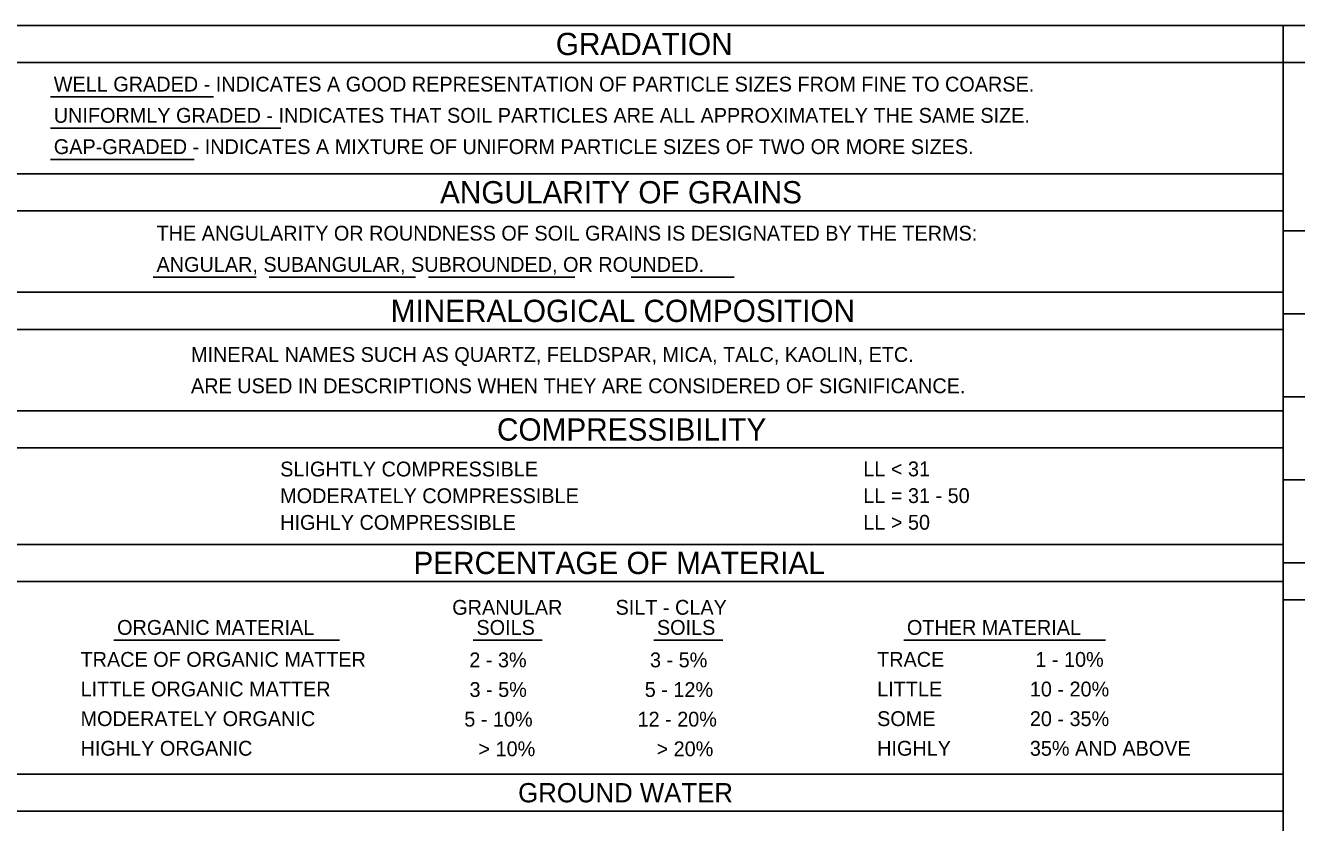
# Model space of a CAD drawing. Extents: x 278618 to 280654, y 171155 to 171855.
# Drawn here: x 280512.35 to 280549.54, y 171598.38 to 171621.7 of the extents above; entities that cross this region are included whole.
import ezdxf

# ---------------------------------------------------------------- set-up
doc = ezdxf.new("R2010")
doc.units = 0
doc.layers.add('Geotech Sheets and Borders Cell', color=7, linetype='Continuous')

msp = doc.modelspace()

# ---------------------------------------------------------------- linework, layer by layer
at = {"layer": 'Geotech Sheets and Borders Cell'}
for p, q in [((280474.148, 171621.702), (280624.148, 171621.702)), ((280549.148, 171621.702), (280549.148, 171541.488)), ((280474.148, 171620.618), (280624.148, 171620.618)), ((280513.086, 171619.609), (280517.847, 171619.609)), ((280513.086, 171618.695), (280519.821, 171618.695)), ((280513.086, 171617.78), (280517.287, 171617.78)), ((280549.148, 171617.364), (280511.888, 171617.364)), ((280549.148, 171616.28), (280511.888, 171616.28)), ((280588.802, 171615.694), (280549.148, 171615.694)), ((280516.091, 171614.334), (280519.104, 171614.334)), ((280519.48, 171614.334), (280523.763, 171614.334)), ((280524.139, 171614.334), (280528.423, 171614.334)), ((280530.069, 171614.334), (280533.082, 171614.334)), ((280549.148, 171613.894), (280511.888, 171613.894)), ((280588.802, 171613.265), (280549.148, 171613.265)), ((280549.148, 171612.809), (280511.888, 171612.809)), ((280588.802, 171610.836), (280549.148, 171610.836)), ((280549.148, 171610.423), (280511.888, 171610.423)), ((280549.148, 171609.339), (280511.888, 171609.339)), ((280588.802, 171608.406), (280549.148, 171608.406)), ((280549.148, 171606.519), (280511.888, 171606.519)), ((280588.802, 171605.977), (280549.148, 171605.977)), ((280549.148, 171605.435), (280511.888, 171605.435)), ((280588.802, 171604.892), (280549.148, 171604.892)), ((280514.937, 171603.714), (280521.536, 171603.714)), ((280525.45, 171603.714), (280527.472, 171603.714)), ((280530.731, 171603.714), (280532.753, 171603.714)), ((280538.046, 171603.714), (280543.949, 171603.714)), ((280549.148, 171599.795), (280511.888, 171599.795)), ((280549.148, 171598.711), (280511.888, 171598.711))]:
    msp.add_line(p, q, dxfattribs=at)

# ---------------------------------------------------------------- texts
for s, height, p in [('GRADATION', 0.6507, (280527.867, 171620.834)), ('WELL GRADED - INDICATES A GOOD REPRESENTATION OF PARTICLE SIZES FROM FINE TO COARSE.', 0.43381, (280513.179, 171619.768)), ('UNIFORMLY GRADED - INDICATES THAT SOIL PARTICLES ARE ALL APPROXIMATELY THE SAME SIZE.', 0.43381, (280513.179, 171618.853)), ('GAP-GRADED - INDICATES A MIXTURE OF UNIFORM PARTICLE SIZES OF TWO OR MORE SIZES.', 0.43381, (280513.179, 171617.938)), ('ANGULARITY OF GRAINS', 0.6507, (280524.48, 171616.496)), ('THE ANGULARITY OR ROUNDNESS OF SOIL GRAINS IS DESIGNATED BY THE TERMS:', 0.43381, (280516.185, 171615.406)), ('ANGULAR, SUBANGULAR, SUBROUNDED, OR ROUNDED.', 0.43381, (280516.185, 171614.492)), ('MINERALOGICAL COMPOSITION', 0.6507, (280523.035, 171613.026)), ('MINERAL NAMES SUCH AS QUARTZ, FELDSPAR, MICA, TALC, KAOLIN, ETC.', 0.43381, (280517.193, 171611.856)), ('ARE USED IN DESCRIPTIONS WHEN THEY ARE CONSIDERED OF SIGNIFICANCE.', 0.43381, (280517.193, 171610.942)), ('COMPRESSIBILITY', 0.6507, (280526.145, 171609.555)), ('SLIGHTLY COMPRESSIBLE', 0.43381, (280519.803, 171608.506)), ('LL < 31', 0.4338, (280536.864, 171608.51)), ('MODERATELY COMPRESSIBLE', 0.43381, (280519.803, 171607.725)), ('LL = 31 - 50', 0.43381, (280536.864, 171607.729)), ('HIGHLY COMPRESSIBLE', 0.43381, (280519.803, 171606.944)), ('LL > 50', 0.4338, (280536.864, 171606.948)), ('PERCENTAGE OF MATERIAL', 0.6507, (280523.701, 171605.651)), ('GRANULAR', 0.4338, (280524.837, 171604.459)), ('SILT - CLAY', 0.43381, (280529.615, 171604.46)), ('ORGANIC MATERIAL', 0.43381, (280515.031, 171603.872)), ('SOILS', 0.4338, (280525.544, 171603.872)), ('SOILS', 0.4338, (280530.825, 171603.872)), ('OTHER MATERIAL', 0.43381, (280538.14, 171603.872)), ('TRACE OF ORGANIC MATTER', 0.43381, (280513.962, 171602.937)), ('2 - 3%', 0.4338, (280525.336, 171602.922)), ('3 - 5%', 0.4338, (280530.623, 171602.922)), ('TRACE', 0.4338, (280537.268, 171602.937)), (' 1 - 10%', 0.4338, (280541.736, 171602.936)), ('LITTLE ORGANIC MATTER', 0.43381, (280513.962, 171602.07)), ('3 - 5%', 0.4338, (280525.342, 171602.055)), ('5 - 12%', 0.4338, (280530.469, 171602.055)), ('LITTLE', 0.4338, (280537.268, 171602.07)), ('10 - 20%', 0.4338, (280541.736, 171602.069)), ('MODERATELY ORGANIC', 0.43381, (280513.962, 171601.203)), ('5 - 10%', 0.4338, (280525.189, 171601.188)), ('12 - 20%', 0.4338, (280530.258, 171601.188)), ('SOME', 0.4338, (280537.268, 171601.203)), ('20 - 35%', 0.4338, (280541.736, 171601.202)), ('HIGHLY ORGANIC', 0.43381, (280513.962, 171600.336)), ('> 10%', 0.4338, (280525.605, 171600.321)), ('> 20%', 0.4338, (280530.814, 171600.321)), ('HIGHLY', 0.4338, (280537.268, 171600.336)), ('35% AND ABOVE', 0.43381, (280541.736, 171600.335)), ('GROUND WATER', 0.56395, (280526.765, 171598.971))]:
    msp.add_text(s, height=height, dxfattribs=at).set_placement(p)

doc.saveas('drawing.dxf')
